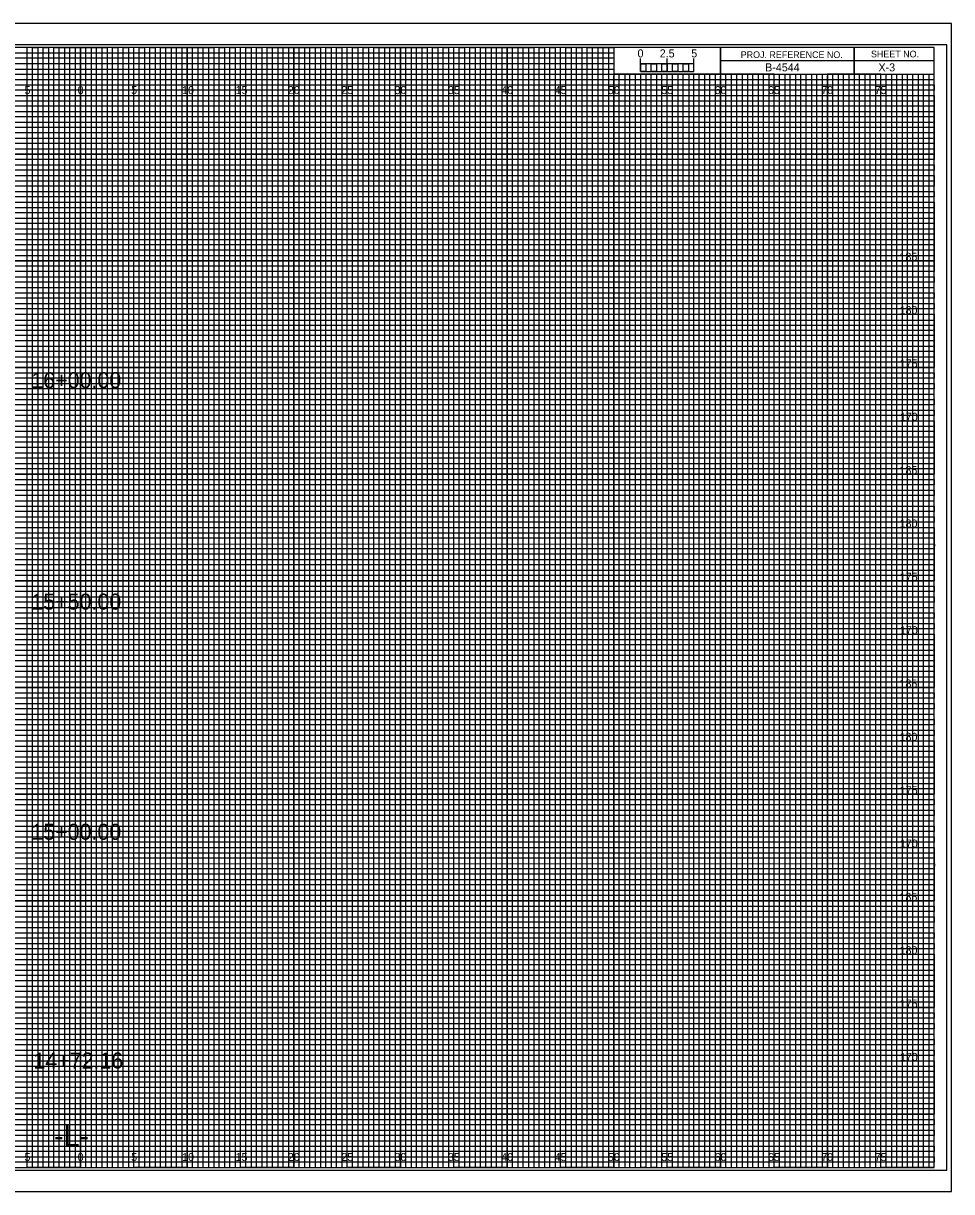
# Model space of a CAD drawing. Extents: x -7 to 162, y -2 to 767.
# Drawn here: x 74.6 to 161.7, y 217.8 to 327.2 of the extents above; entities that cross this region are included whole.
import ezdxf

# ---------------------------------------------------------------- set-up
doc = ezdxf.new("R2010")
doc.units = 0
for name, color, linetype in [('Exist CMT Pavement', 7, 'Continuous'), ('Exist Cross Section Cell', 7, 'Continuous'), ('Exist XS Ground Line', 7, 'Continuous'), ('Prop CMT Pvmt Course 1', 7, 'Continuous'), ('Prop CMT Pvmt Course 1 Wedge', 7, 'Continuous'), ('Prop CMT Pvmt Course 2', 7, 'Continuous'), ('Prop CMT Pvmt Course 2 Wedge', 7, 'Continuous'), ('Prop CMT Pvmt Course 3', 7, 'Continuous'), ('Prop CMT Pvmt Course 3 Wedge', 7, 'Continuous'), ('Prop CMT Pvmt Surface', 7, 'Continuous'), ('Prop CMT Pvmt Surface Shoulder', 7, 'Continuous'), ('Prop CMT Shld Paved Course 1', 7, 'Continuous'), ('Prop CMT Shld Paved Course 2', 7, 'Continuous'), ('Prop CMT Shld Paved Course 3', 7, 'Continuous'), ('Prop CMT Slope Grass', 7, 'Continuous'), ('Prop CMT Subgrade Earthwork', 7, 'Continuous'), ('Scratch_Level_0', 7, 'Continuous')]:
    doc.layers.add(name, color=color, linetype=linetype)

msp = doc.modelspace()

# ---------------------------------------------------------------- linework, layer by layer
at = {"layer": 'Prop CMT Pvmt Course 1'}
for p, q in [((0, 324.5), (130, 324.5)), ((130, 324.5), (130, 323.99)), ((130, 323.99), (0, 323.99)), ((0, 323.5), (130, 323.5)), ((130, 323.5), (130, 322.94)), ((130, 322.94), (0, 322.94)), ((0, 322), (160, 322))]:
    msp.add_line(p, q, dxfattribs=at)
for points in [[(0, 321.5), (135, 321.5), (160, 321.5), (160, 321), (0, 321)], [(0, 320.5), (160, 320.5), (160, 319.5), (0, 319.5)], [(0, 319), (160, 319), (160, 318.5), (0, 318.49)], [(0, 318), (160, 318), (160, 317), (0, 317)], [(0, 316.5), (160, 316.5), (160, 316), (0, 316)], [(0, 315.5), (160, 315.5), (160, 314.5), (0, 314.5)], [(0, 314), (160, 314), (160, 313.5), (0, 313.5)], [(0, 313), (160, 313), (160, 312), (0, 312)], [(0, 311.5), (160, 311.5), (160, 311), (0, 311)], [(0, 310.5), (160, 310.5), (160, 309.5), (0, 309.5)], [(0, 309), (160, 309), (160, 308.5), (0, 308.5)], [(0, 308), (160, 308), (160, 306.98), (160, 306.5), (160, 306), (0, 306)], [(0, 307), (160, 307), (160, 306.5), (0, 306.5)], [(0, 305.5), (160, 305.5), (160, 304.5), (0, 304.51)], [(0, 304.51), (160, 304.5), (160, 304), (0, 304)], [(0, 303.5), (160, 303.5), (160, 303), (0, 303)], [(0, 302), (160, 302), (160, 301.5), (0, 301.5)], [(0, 301), (160, 301), (160, 300.5), (0, 300.5)], [(-0.04, 299.44), (160, 299.44), (160, 298.94), (-0.04, 298.94)], [(0, 298.5), (160, 298.5), (160, 298), (0, 298)], [(0, 297), (160, 297), (160, 296.5), (0, 296.5)], [(0, 296), (160, 296), (160, 295.5), (0, 295.5)], [(0, 294.5), (160, 294.5), (160, 294), (0, 294)], [(0, 293.5), (160, 293.5), (160, 293), (0, 293)], [(0, 292), (160, 292), (160, 291.5), (0, 291.5)], [(0, 291), (160, 291), (160, 290.5), (0, 290.5)], [(0, 289.5), (160, 289.5), (160, 288.99), (0, 289)], [(0, 288.5), (160, 288.5), (160, 288), (0, 288)], [(0, 287), (160, 287), (160, 286.5), (0, 286.5)], [(0, 286), (160, 286), (160, 285.5), (0, 285.5)], [(0, 284.5), (160, 284.5), (160, 284), (0, 284)], [(0, 283.5), (160, 283.5), (160, 283), (0, 283)], [(0, 282), (160, 282), (160, 281.5), (0, 281.5)], [(0, 281), (160, 281), (160, 280.5), (0, 280.5)], [(0, 279.5), (160, 279.5), (160, 279), (0, 279)], [(0, 278.5), (160.03, 278.45), (160, 278), (0, 278)], [(0, 277), (160, 277), (160, 276.5), (0, 276.5)], [(0, 276), (160, 276), (160, 275.5), (0, 275.5)], [(0, 274.5), (160, 274.5), (160, 274), (0, 274)], [(0, 273.5), (160, 273.5), (160, 273), (0, 273)], [(0, 272), (160, 272), (160, 271.5), (0, 271.5)], [(0, 271), (160, 271), (160, 270.5), (0, 270.5)], [(0, 269.5), (160, 269.5), (160, 269), (0, 269)], [(0, 268.5), (160, 268.5), (160, 268), (0, 268)], [(0, 267), (160, 267), (160, 266.5), (0, 266.5)], [(0, 266), (160, 266), (160, 265.5), (0, 265.5)], [(0, 264.5), (160, 264.5), (160, 264), (0, 264)], [(0, 263.5), (160, 263.5), (160, 263), (0, 263)], [(0, 262), (160, 262), (160, 261.5), (0, 261.5)], [(0, 261), (160, 261), (160, 260.5), (0, 260.5)], [(0, 259.5), (160, 259.5), (160, 258.99), (0, 259)], [(0, 258.5), (160, 258.5), (160, 258), (0, 258)], [(0, 257), (160, 257), (160, 256.5), (0, 256.5)], [(0, 256), (160, 256), (160, 255.5), (0, 255.5)], [(0, 254.5), (160, 254.5), (160, 254), (0, 254)], [(0, 253.5), (160, 253.5), (160, 253), (0, 253)], [(0, 252), (160, 252), (160, 251.5), (0, 251.5)], [(0, 251), (160, 251), (160, 250.5), (0, 250.5)], [(0, 249.5), (160, 249.5), (160, 249), (0, 249)], [(0, 248.5), (160.03, 248.46), (160, 248), (0, 248)], [(0, 247), (160, 247), (160, 246.5), (0, 246.5)], [(0, 246), (160, 246), (160, 245.5), (0, 245.5)], [(0, 244.5), (160, 244.5), (160, 244), (0, 244)], [(0, 243.5), (160, 243.5), (160, 243), (0, 243)], [(0, 242), (160, 242), (160, 241.5), (0, 241.5)], [(0, 241), (160, 241), (160, 240.5), (0, 240.5)], [(0, 239.5), (160, 239.5), (160, 239), (0, 239)], [(0, 238.5), (160, 238.5), (160, 238), (0, 238)], [(0, 237), (160, 237), (160, 236.5), (0, 236.5)], [(0, 236), (160, 236), (160, 235.5), (0, 235.5)], [(0, 234.5), (160, 234.5), (160, 234), (0, 234)], [(0, 233.5), (160, 233.5), (160, 233), (0, 233)], [(0, 232), (160, 232), (160, 231.5), (0, 231.5)], [(0, 231), (160, 231), (160, 230.5), (0, 230.5)], [(0, 229.5), (160, 229.5), (160, 229), (0, 229)], [(0, 228.5), (160, 228.5), (160, 228), (0, 228)], [(0, 227), (160, 227), (160, 226.5), (0, 226.5)], [(0, 226), (160, 226), (160, 225.5), (0, 225.5)], [(0, 224.5), (160, 224.5), (160, 224), (0, 224)], [(0, 223.5), (160, 223.5), (160, 223), (0, 223)], [(0, 222), (160, 222), (160, 221.5), (0, 221.5)], [(0, 221), (160, 221), (160, 220.5), (0, 220.5)]]:
    msp.add_lwpolyline(points, dxfattribs=at)
at = {"layer": 'Prop CMT Pvmt Course 2'}
for p, q in [((75, 220), (75, 325)), ((80, 220), (80, 325)), ((85, 220), (85, 325)), ((90, 220), (90, 325)), ((95, 220), (95, 325)), ((100, 220), (100, 325)), ((105, 220), (105, 325)), ((110, 220), (110, 325)), ((115, 220), (115, 325)), ((120, 220), (120, 325)), ((125, 220), (125, 325)), ((130, 220), (130, 322.34)), ((135, 220), (135, 322.34)), ((140, 220), (140, 322.34)), ((145, 220), (145, 322.34)), ((150, 220), (150, 322.34)), ((155, 220), (155, 322.34)), ((0, 320), (160, 320)), ((0, 315), (160, 315)), ((0, 310), (160, 310)), ((0, 305), (160, 305)), ((0, 300), (160, 300)), ((0, 295), (160, 295)), ((0, 290), (160, 290)), ((0, 285), (160, 285)), ((0, 280), (160, 280)), ((0, 275), (160, 275)), ((0, 270), (160, 270)), ((0, 265), (160, 265)), ((0, 260), (160, 260)), ((0, 255), (160, 255)), ((0, 250), (160, 250)), ((0, 245), (160, 245)), ((0, 240), (160, 240)), ((0, 235), (160, 235)), ((0, 230), (160, 230)), ((0, 225), (160, 225))]:
    msp.add_line(p, q, dxfattribs=at)
at = {"layer": 'Prop CMT Pvmt Course 3'}
for p, q in [((161.65, 327.25), (-6.7, 327.25)), ((-6.7, 217.75), (161.65, 217.75))]:
    msp.add_line(p, q, dxfattribs=at)
at = {"layer": 'Prop CMT Pvmt Surface Shoulder'}
for points in [[(72.5, 220), (77.5, 220), (77.5, 325), (82.5, 325), (82.5, 220), (87.5, 220), (87.5, 325), (92.5, 325), (92.5, 220), (97.5, 220), (97.5, 325), (102.5, 325), (102.5, 220), (107.5, 220), (107.5, 325), (112.5, 325), (112.5, 220), (117.5, 220), (117.5, 325), (122.5, 325), (122.5, 220), (127.5, 220), (127.5, 325), (129.97, 325), (130, 325), (130, 322.5), (132.5, 322.5), (132.5, 220), (137.5, 220), (137.5, 322.5), (142.5, 322.5), (142.5, 220), (147.5, 220), (147.5, 322.5), (152.5, 322.5), (152.5, 220), (157.5, 220), (157.5, 322.5)], [(0, 322.5), (137.5, 322.5)], [(0, 312.5), (160, 312.5), (160, 317.5), (0, 317.5)], [(0, 302.5), (160, 302.5), (160, 307.5), (0, 307.5)], [(0, 292.5), (160, 292.5), (160, 297.5), (0, 297.5)], [(0, 282.5), (160, 282.5), (160, 287.5), (0, 287.5)], [(0, 272.5), (160, 272.5), (160, 277.5), (0, 277.5)], [(0, 262.5), (160, 262.5), (160, 267.5), (0, 267.5)], [(0, 252.5), (160, 252.5), (160, 257.5), (0, 257.5)], [(0, 242.5), (160, 242.5), (160, 247.5), (0, 247.5)], [(0, 232.5), (160, 232.5), (160, 237.5), (0, 237.5)], [(0, 222.5), (160, 222.5), (160, 227.5), (0, 227.5)]]:
    msp.add_lwpolyline(points, dxfattribs=at)
at = {"layer": 'Prop CMT Shld Paved Course 1'}
for p, q in [((132.5, 322.75), (132.5, 323.95)), ((132.5, 323.45), (132.5, 323.95)), ((135, 322.75), (135, 323.95)), ((137.5, 322.75), (137.5, 323.95)), ((137.5, 323.45), (137.5, 323.95))]:
    msp.add_line(p, q, dxfattribs=at)
for points in [[(137.5, 323.45), (132.5, 323.45), (132.5, 322.75), (137.5, 322.75)], [(132.5, 323.45), (133, 323.45), (133, 322.75), (132.5, 322.75)], [(133.5, 323.45), (134, 323.45), (134, 322.75), (133.5, 322.75)], [(134.5, 323.45), (135, 323.45), (135, 322.75), (134.5, 322.75)], [(135.5, 323.45), (136, 323.45), (136, 322.75), (135.5, 322.75)], [(136.5, 323.45), (137, 323.45), (137, 322.75), (136.5, 322.75)]]:
    msp.add_lwpolyline(points, close=True, dxfattribs=at)
at = {"layer": 'Prop CMT Shld Paved Course 2'}
msp.add_lwpolyline([(-6.7, 217.75), (161.65, 217.75), (161.65, 327.25), (-6.7, 327.25)], close=True, dxfattribs=at)
at = {"layer": 'Prop CMT Shld Paved Course 3'}
msp.add_lwpolyline([(-5.4, 219.75), (161.2, 219.75), (161.2, 325.25), (-5.4, 325.25)], close=True, dxfattribs=at)
at = {"layer": 'Prop CMT Slope Grass'}
for p, q in [((133.5, 322.5), (133, 322.5)), ((133, 322.5), (133, 220)), ((133.5, 220), (133.5, 322.5)), ((134.5, 322.5), (134, 322.5)), ((134, 322.5), (134, 220)), ((134.5, 220), (134.5, 322.5)), ((133, 220), (132.5, 220)), ((134, 220), (133.5, 220))]:
    msp.add_line(p, q, dxfattribs=at)
for points in [[(75, 220), (75.5, 220), (75.5, 325), (76, 325), (76, 220)], [(76, 220), (76.5, 220), (76.5, 325), (77, 325), (77, 220)], [(77.5, 220), (78, 220), (78, 325), (78.5, 325), (78.5, 220)], [(78.5, 220), (79, 220), (79, 325), (79.5, 325), (79.5, 220)], [(80, 220), (80.5, 220), (80.5, 325), (81, 325), (81, 220)], [(81, 220), (81.5, 220), (81.5, 325), (82, 325), (82, 220)], [(82.5, 220), (83, 220), (83, 325), (83.5, 325), (83.5, 220)], [(83.5, 220), (84, 220), (84, 325), (84.5, 325), (84.5, 220)], [(85, 220), (85.5, 220), (85.5, 325), (86, 325), (86, 220)], [(86, 220), (86.5, 220), (86.5, 325), (87, 325), (87, 220)], [(87.5, 220), (88, 220), (88, 325), (88.5, 325), (88.5, 220)], [(88.5, 220), (89, 220), (89, 325), (89.5, 325), (89.5, 220)], [(90, 220), (90.5, 220), (90.5, 325), (91, 325), (91, 220)], [(91, 220), (91.5, 220), (91.5, 325), (92, 325), (92, 220)], [(92.5, 220), (93, 220), (93, 325), (93.5, 325), (93.5, 220)], [(93.5, 220), (94, 220), (94, 325), (94.5, 325), (94.5, 220)], [(95, 220), (95.5, 220), (95.5, 325), (96, 325), (96, 220)], [(96, 220), (96.5, 220), (96.5, 325), (97, 325), (97, 220)], [(97.5, 220), (98, 220), (98, 325), (98.5, 325), (98.5, 220)], [(98.5, 220), (99, 220), (99, 325), (99.5, 325), (99.5, 220)], [(100, 220), (100.5, 220), (100.5, 325), (101, 325), (101, 220)], [(101, 220), (101.5, 220), (101.5, 325), (102, 325), (102, 220)], [(102.5, 220), (103, 220), (103, 325), (103.5, 325), (103.5, 220)], [(103.5, 220), (104, 220), (104, 325), (104.5, 325), (104.5, 220)], [(105, 220), (105.5, 220), (105.5, 325), (106, 325), (106, 220)], [(106, 220), (106.5, 220), (106.5, 325), (107, 325), (107, 220)], [(107.5, 220), (108, 220), (108, 325), (108.5, 325), (108.5, 220)], [(108.5, 220), (109, 220), (109, 325), (109.5, 325), (109.5, 220)], [(110, 220), (110.5, 220), (110.5, 325), (111, 325), (111, 220)], [(111, 220), (111.5, 220), (111.5, 325), (112, 325), (112, 220)], [(112.5, 220), (113, 220), (113, 325), (113.5, 325), (113.5, 220)], [(113.5, 220), (114, 220), (114, 325), (114.5, 325), (114.5, 220)], [(115, 220), (115.5, 220), (115.5, 325), (116, 325), (116, 220)], [(116, 220), (116.5, 220), (116.5, 325), (117, 325), (117, 220)], [(117.5, 220), (118, 220), (118, 325), (118.5, 325), (118.5, 220)], [(118.5, 220), (119, 220), (119, 325), (119.5, 325), (119.5, 220)], [(120, 220), (120.5, 220), (120.5, 325), (121, 325), (121, 220)], [(121, 220), (121.5, 220), (121.5, 325), (122, 325), (122, 220)], [(122.5, 220), (123, 220), (123, 325), (123.5, 325), (123.5, 220)], [(123.5, 220), (124, 220), (124, 325), (124.5, 325), (124.5, 220)], [(125, 220), (125.5, 220), (125.5, 325), (126, 325), (126, 220)], [(126, 220), (126.5, 220), (126.5, 325), (127, 325), (127, 220)], [(127.5, 220), (128, 220), (128, 325), (128.5, 325), (128.5, 220)], [(128.5, 220), (129, 220), (129, 325), (129.5, 325), (129.5, 220)], [(130, 220), (130.5, 220), (130.5, 322.5), (131.01, 322.5), (131.01, 220)], [(131, 220), (131.5, 220), (131.5, 322.5), (132, 322.5), (132, 220)], [(135, 220), (135.49, 220), (135.49, 322.5), (136, 322.5), (136, 220)], [(136, 220), (136.5, 220), (136.5, 322.5), (137.03, 322.5), (137.03, 220)], [(137.5, 220), (138, 220), (138, 322.5), (138.5, 322.5), (138.5, 220)], [(138.5, 220), (139, 220), (139, 322.5), (139.5, 322.5), (139.5, 220)], [(140, 220), (140.5, 220), (140.5, 322.5), (141, 322.5), (141, 220)], [(141, 220), (141.5, 220), (141.5, 322.5), (142, 322.5), (142, 220)], [(142.5, 220), (143, 220), (143, 322.5), (143.5, 322.5), (143.5, 220)], [(143.5, 220), (144, 220), (144, 322.5), (144.5, 322.5), (144.5, 220)], [(145, 220), (145.5, 220), (145.5, 322.5), (146, 322.5), (146, 220)], [(146, 220), (146.5, 220), (146.5, 322.5), (147, 322.5), (147, 220)], [(147.5, 220), (148, 220), (148, 322.5), (148.5, 322.5), (148.5, 220)], [(148.5, 220), (149, 220), (149, 322.5), (149.5, 322.5), (149.5, 220)], [(150, 220), (150.5, 220), (150.5, 322.5), (151, 322.5), (151, 220)], [(151, 220), (151.5, 220), (151.5, 322.5), (152, 322.5), (152, 220)], [(152.5, 220), (153, 220), (153, 322.5), (153.5, 322.5), (153.5, 220)], [(153.5, 220), (154, 220), (154, 322.5), (154.5, 322.5), (154.5, 220)], [(155, 220), (155.5, 220), (155.5, 322.5), (156, 322.5), (156, 220)], [(156, 220), (156.5, 220), (156.5, 322.5), (157, 322.5), (157, 220)], [(157.5, 220), (158, 220), (158, 322.5), (158.5, 322.5), (158.5, 220)], [(158.5, 220), (159, 220), (159, 322.5), (159.5, 322.5), (159.5, 220)]]:
    msp.add_lwpolyline(points, dxfattribs=at)
at = {"layer": 'Prop CMT Subgrade Earthwork'}
for p, q in [((152.5, 325), (152.5, 322.5)), ((152.5, 322.5), (152.5, 325)), ((160, 323.75), (140, 323.75)), ((140, 323.75), (140, 322.5)), ((140, 322.5), (160, 322.5))]:
    msp.add_line(p, q, dxfattribs=at)
for points in [[(160, 325), (0, 325), (0, 220), (160, 220)], [(140, 325), (130, 325), (130, 322.51), (140, 322.51)], [(160, 325), (140, 325), (140, 322.5), (160, 322.5)]]:
    msp.add_lwpolyline(points, close=True, dxfattribs=at)
at = {"layer": 'Scratch_Level_0'}
for p, q in [((75, 325), (70, 325)), ((75, 220), (75, 325)), ((85, 325), (80, 325)), ((80, 325), (80, 220)), ((85, 220), (85, 325)), ((95, 325), (90, 325)), ((90, 325), (90, 220)), ((95, 220), (95, 325)), ((105, 325), (100, 325)), ((100, 325), (100, 220)), ((105, 220), (105, 325)), ((115, 325), (110, 325)), ((110, 325), (110, 220)), ((115, 220), (115, 325)), ((125, 325), (120, 325)), ((120, 325), (120, 220)), ((125, 220), (125, 325)), ((130, 325), (130, 220)), ((135, 220), (135, 322.5)), ((145, 322.5), (140, 322.5)), ((140, 322.5), (140, 220)), ((145, 220), (145, 322.5)), ((155, 322.5), (150, 322.5)), ((150, 322.5), (150, 220)), ((155, 220), (155, 322.5)), ((80, 220), (75, 220)), ((90, 220), (85, 220)), ((100, 220), (95, 220)), ((110, 220), (105, 220)), ((120, 220), (115, 220)), ((130, 220), (125, 220)), ((140, 220), (135, 220)), ((150, 220), (145, 220)), ((160, 220), (155, 220)), ((160, 220), (160, 220))]:
    msp.add_line(p, q, dxfattribs=at)
for points in [[(0, 320), (160, 320), (160, 315), (0, 315)], [(0, 310), (160, 310), (160, 305), (0, 305)], [(0, 300), (160, 300), (160, 295), (0, 295)], [(0, 290), (160, 290), (160, 285), (0, 285)], [(0, 280), (160, 280), (160, 275), (0, 275)], [(0, 270), (160, 270), (160, 265), (0, 265)], [(0, 260), (160, 260), (160, 255), (0, 255)], [(0, 250), (160, 250), (160, 245), (0, 245)], [(0, 240), (160, 240), (160, 235), (0, 235)], [(0, 230), (160, 230), (160, 225), (0, 225)]]:
    msp.add_lwpolyline(points, dxfattribs=at)

# ---------------------------------------------------------------- texts
at = {"layer": 'Exist CMT Pavement'}
msp.add_text('B-4544', height=0.75, dxfattribs=at).set_placement((144.17, 322.75))
at = {"layer": 'Exist Cross Section Cell'}
for s, p in [('5', (74.74, 320.62)), ('0', (79.73, 320.62)), ('0', (79.73, 320.62)), ('5', (84.74, 320.62)), ('10', (89.52, 320.62)), ('15', (94.53, 320.62)), ('20', (99.43, 320.62)), ('25', (104.44, 320.62)), ('30', (109.43, 320.62)), ('35', (114.44, 320.62)), ('40', (119.43, 320.62)), ('45', (124.44, 320.62)), ('50', (129.43, 320.62)), ('55', (134.44, 320.62)), ('60', (139.43, 320.62)), ('65', (144.44, 320.62)), ('70', (149.43, 320.62)), ('75', (154.44, 320.62)), ('5', (74.74, 220.62)), ('0', (79.73, 220.62)), ('0', (79.73, 220.62)), ('5', (84.74, 220.62)), ('10', (89.52, 220.62)), ('15', (94.53, 220.62)), ('20', (99.43, 220.62)), ('25', (104.44, 220.62)), ('30', (109.43, 220.62)), ('35', (114.44, 220.62)), ('40', (119.43, 220.62)), ('45', (124.44, 220.62)), ('50', (129.43, 220.62)), ('55', (134.44, 220.62)), ('60', (139.43, 220.62)), ('65', (144.44, 220.62)), ('70', (149.43, 220.62)), ('75', (154.44, 220.62))]:
    msp.add_text(s, height=0.75, dxfattribs=at).set_placement(p)
at = {"layer": 'Exist XS Ground Line'}
for s, p in [('2.5', (134.29, 324.06)), ('5', (137.24, 324.06))]:
    msp.add_text(s, height=0.75, dxfattribs=at).set_placement(p)
at = {"layer": 'Prop CMT Pvmt Course 1 Wedge'}
for s, p in [('185', (156.76, 305)), ('180', (156.77, 300)), ('175', (156.79, 295)), ('170', (156.8, 290)), ('185', (156.76, 285)), ('180', (156.77, 280)), ('175', (156.79, 275)), ('170', (156.8, 270)), ('185', (156.76, 265)), ('180', (156.77, 260)), ('175', (156.79, 255)), ('170', (156.8, 250)), ('185', (156.76, 245)), ('180', (156.77, 240)), ('175', (156.79, 235)), ('170', (156.8, 230))]:
    msp.add_text(s, height=0.75, dxfattribs=at).set_placement(p)
at = {"layer": 'Prop CMT Pvmt Course 2 Wedge'}
for s, p in [('16+00.00', (75.39, 293.06)), ('15+50.00', (75.39, 272.3)), ('15+00.00', (75.39, 250.73)), ('14+72.16', (75.58, 229.29))]:
    msp.add_text(s, height=1.5, dxfattribs=at).set_placement(p)
at = {"layer": 'Prop CMT Pvmt Course 3 Wedge'}
msp.add_text('X-3', height=0.75, dxfattribs=at).set_placement((154.79, 322.75))
at = {"layer": 'Prop CMT Pvmt Surface'}
msp.add_text('-L-', height=2, dxfattribs=at).set_placement((77.53, 222))
at = {"layer": 'Prop CMT Shld Paved Course 1'}
msp.add_text('0', height=0.75, dxfattribs=at).set_placement((132.21, 324.06))
at = {"layer": 'Prop CMT Subgrade Earthwork'}
for s, p in [('PROJ. REFERENCE NO.', (141.88, 324)), ('SHEET NO.', (154.09, 324.06))]:
    msp.add_text(s, height=0.625, dxfattribs=at).set_placement(p)

doc.saveas('drawing.dxf')
